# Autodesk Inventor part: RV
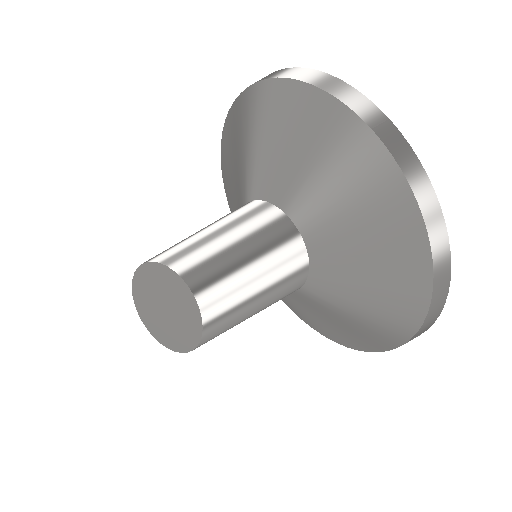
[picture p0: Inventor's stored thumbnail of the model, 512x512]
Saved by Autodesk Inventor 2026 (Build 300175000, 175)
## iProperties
Created: 2004-09
Part Number: RV
Document SubType Name: Modeling
Designer: Lars Bertram Pedersen
Manufacturer: Standard
Standards Organization: Custom
Material: Steel, Mild
Density: 7.85 g/cm^3
Appearance: Semi-Polished
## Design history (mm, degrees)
revolve "Revolution2" stored, may be unused: angle "d8" = 90 deg
body "Solid2"
sketch "Sketch1"
  geometry: L1 (0, 100)-(60, 100); L2 (60, 100)-(60, 90); L3 (60, 90)-(20, 60); L4 (20, 60)-(20, 0); L5 (20, 0)-(0, 0); L6 (0, 0)-(0, 100); 1 further point
  constraints: 12 end point, 3 parallel, 1 coincident, 1 horizontal, 1 perpendicular
  dimensions: "d0" = 10 distance of L1.end L2.end; "d3" = 60 distance of L3.end L4.end; "d4" = 100 distance of L5.end L1.start; "d6" = 120 diameter of L2 L6; "d7" = 40 diameter of L4 L6
